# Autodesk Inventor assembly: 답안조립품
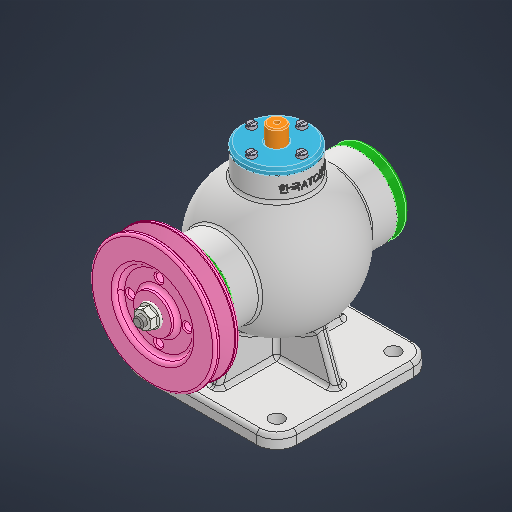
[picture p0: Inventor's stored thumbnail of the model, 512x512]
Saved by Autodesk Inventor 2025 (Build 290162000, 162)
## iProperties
Created: 2025-08
Part Number: 답안조립품
Document SubType Name: Assembly
Designer: infra002
Author: infra002
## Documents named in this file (15)
- C:\Users\infra002\Desktop\750807V1012\답안조립품.iam
- C:\Users\infra002\Desktop\750807V1012\V-벨트풀리\V-벨트풀리.ipt
- C:\Users\infra002\Desktop\750807V1012\너트 M8\너트 M8.ipt
- C:\Users\infra002\Desktop\750807V1012\뒤커버\뒤커버.ipt
- C:\Users\infra002\Desktop\750807V1012\베어링- 6202\베어링- 6202.ipt
- C:\Users\infra002\Desktop\750807V1012\볼트 M4 x 12\볼트 M4 x 12.ipt
- C:\Users\infra002\Desktop\750807V1012\볼트 M4 x 16\볼트 M4 x 16.ipt
- C:\Users\infra002\Desktop\750807V1012\상부커버\상부커버.ipt
- C:\Users\infra002\Desktop\750807V1012\슬라이드\슬라이드.ipt
- C:\Users\infra002\Desktop\750807V1012\앞커버\앞커버.ipt
- C:\Users\infra002\Desktop\750807V1012\오일실 15 30 7\오일실 15 30 7.ipt
- C:\Users\infra002\Desktop\750807V1012\칼라\칼라.ipt
- C:\Users\infra002\Desktop\750807V1012\키 4 x 4 x 12\키 4 x 4 x 12.ipt
- C:\Users\infra002\Desktop\750807V1012\편심축\편심축.ipt
- C:\Users\infra002\Desktop\750807V1012\본체.ipt
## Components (1 placed, 1 different names)
1. V-벨트풀리:1
